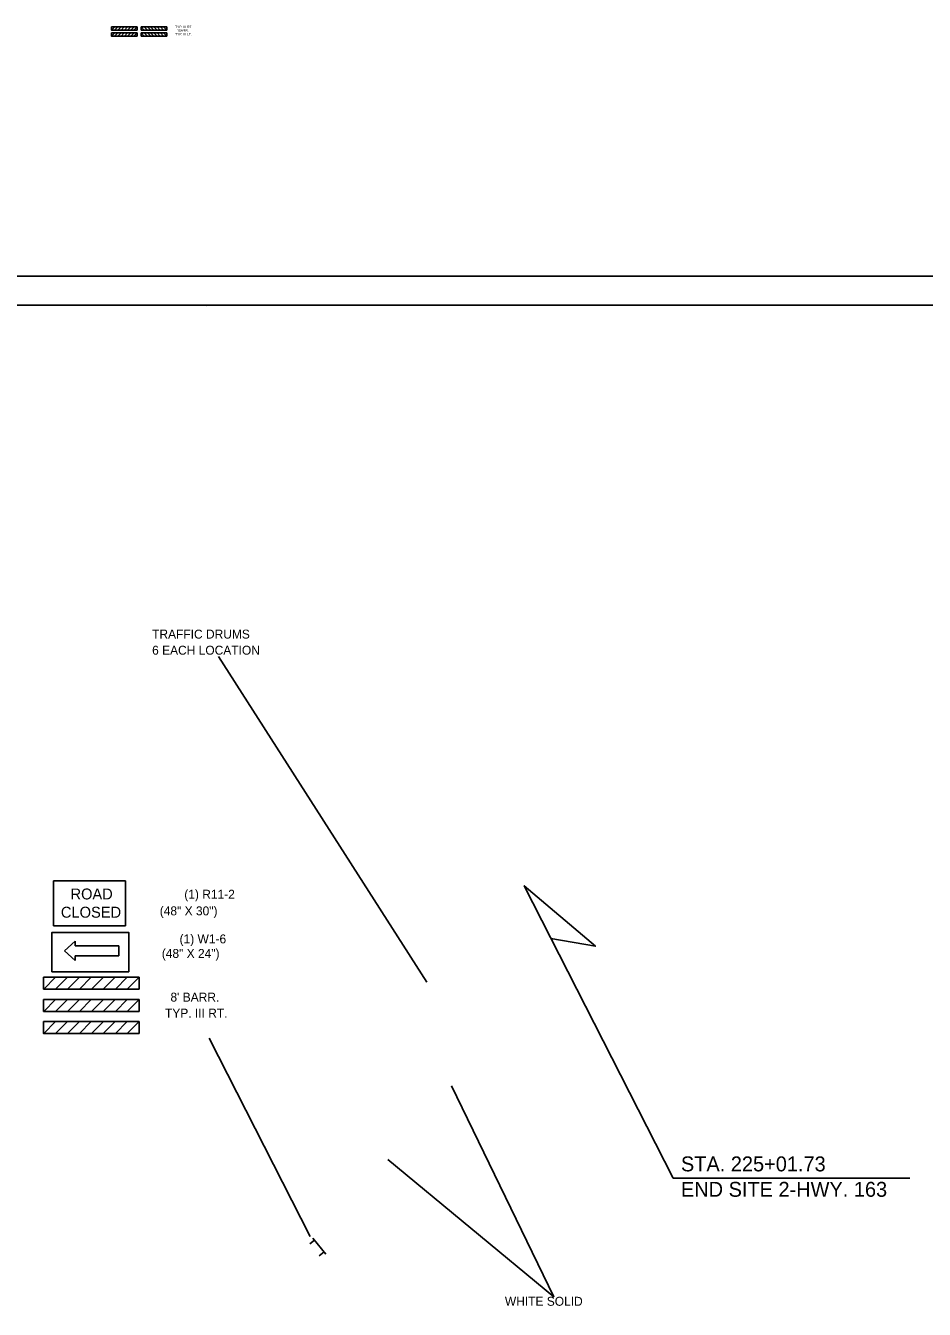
# Model space of a CAD drawing. Extents: x 1678017 to 1687792, y 404433 to 413488.
# Drawn here: x 1682454 to 1683056, y 409484 to 410344 of the extents above; entities that cross this region are included whole.
import ezdxf

# ---------------------------------------------------------------- set-up
doc = ezdxf.new("R2010")
doc.units = 0
for name, color, linetype in [('Default', 7, 'Continuous'), ('S_BUILDING', 7, 'Continuous'), ('S_GRAVEL_ROAD', 7, 'Continuous'), ('S_STREAM', 7, 'Continuous')]:
    doc.layers.add(name, color=color, linetype=linetype)

msp = doc.modelspace()

# ---------------------------------------------------------------- linework, layer by layer
at = {"layer": 'Default'}
for p, q in [((1682582.96, 409921.64), (1682722.71, 409703.28)), ((1682576.67, 409665.79), (1682644.35, 409532.72)), ((1682887.63, 409571.96), (1683046.44, 409571.96))]:
    msp.add_line(p, q, dxfattribs=at)
msp.add_lwpolyline([(1682887.63, 409571.96), (1682787.92, 409767.83), (1682835.6, 409727.36), (1682805.82, 409732.48)], dxfattribs=at)
at = {"layer": 'S_BUILDING'}
for p, q in [((1681812.23, 410157.15), (1683393.13, 410157.15)), ((1682574.83, 410155.85), (1682574.83, 410155.85)), ((1682574.83, 410155.85), (1682574.83, 410155.85))]:
    msp.add_line(p, q, dxfattribs=at)
at = {"layer": 'S_GRAVEL_ROAD'}
for p, q in [((1682511.17, 410343.63), (1682528.46, 410343.63)), ((1682511.17, 410341.46), (1682511.17, 410343.63)), ((1682511.17, 410341.46), (1682528.46, 410341.46)), ((1682528.46, 410341.46), (1682528.46, 410343.63)), ((1682528.46, 410341.46), (1682528.46, 410343.63)), ((1682548.31, 410343.63), (1682531.03, 410343.63)), ((1682531.03, 410341.46), (1682531.03, 410343.63)), ((1682531.03, 410341.46), (1682531.03, 410343.63)), ((1682548.31, 410341.46), (1682531.03, 410341.46)), ((1682548.31, 410341.46), (1682548.31, 410343.63)), ((1682511.17, 410339.62), (1682528.46, 410339.62)), ((1682511.17, 410337.45), (1682511.17, 410339.62)), ((1682511.17, 410337.45), (1682528.46, 410337.45)), ((1682528.46, 410337.45), (1682528.46, 410339.62)), ((1682548.31, 410339.62), (1682531.03, 410339.62)), ((1682531.03, 410337.45), (1682531.03, 410339.62)), ((1682548.31, 410337.45), (1682531.03, 410337.45)), ((1682548.31, 410337.45), (1682548.31, 410339.62)), ((1682472.43, 409741), (1682472.43, 409771.18)), ((1682472.43, 409771.18), (1682520.73, 409771.18)), ((1682520.73, 409741), (1682520.73, 409771.18)), ((1682472.43, 409741), (1682520.73, 409741)), ((1682479.67, 409724.27), (1682486.84, 409730.81)), ((1682486.84, 409727.54), (1682486.84, 409730.81)), ((1682486.84, 409717.72), (1682479.67, 409724.27)), ((1682516.23, 409727.54), (1682486.84, 409727.54)), ((1682516.23, 409720.99), (1682486.84, 409720.99)), ((1682486.84, 409720.99), (1682486.84, 409717.72)), ((1682516.23, 409720.99), (1682516.23, 409727.54)), ((1682465.65, 409706.59), (1682529.71, 409706.59)), ((1682465.65, 409698.54), (1682465.65, 409706.59)), ((1682529.71, 409698.54), (1682529.71, 409706.59)), ((1682465.65, 409698.54), (1682529.71, 409698.54)), ((1682529.66, 409698.57), (1682529.71, 409698.61)), ((1682465.65, 409691.67), (1682529.71, 409691.67)), ((1682465.65, 409683.65), (1682465.65, 409691.67)), ((1682529.71, 409683.65), (1682529.71, 409691.67)), ((1682529.71, 409683.65), (1682529.71, 409691.67)), ((1682465.65, 409683.65), (1682529.71, 409683.65)), ((1682465.65, 409676.81), (1682529.71, 409676.81)), ((1682465.65, 409668.79), (1682465.65, 409676.81)), ((1682529.71, 409668.79), (1682529.71, 409676.81)), ((1682465.65, 409668.79), (1682529.71, 409668.79)), ((1682646.27, 409531.71), (1682654.99, 409520.96)), ((1682647.37, 409530.36), (1682644.11, 409527.72)), ((1682653.8, 409522.42), (1682650.54, 409519.78))]:
    msp.add_line(p, q, dxfattribs=at)
for points in [[(1682515.5, 410343.63), (1682513.38, 410343.62), (1682511.22, 410341.46), (1682513.34, 410341.46)], [(1682519.82, 410343.63), (1682517.7, 410343.62), (1682515.54, 410341.46), (1682517.66, 410341.46)], [(1682524.14, 410343.63), (1682522.02, 410343.62), (1682519.86, 410341.46), (1682521.98, 410341.46)], [(1682528.46, 410343.63), (1682526.34, 410343.62), (1682524.18, 410341.46), (1682526.3, 410341.46)], [(1682531.03, 410343.63), (1682533.15, 410343.62), (1682535.31, 410341.46), (1682533.19, 410341.46)], [(1682535.35, 410343.63), (1682537.47, 410343.62), (1682539.63, 410341.46), (1682537.51, 410341.46)], [(1682539.67, 410343.63), (1682541.79, 410343.62), (1682543.95, 410341.46), (1682541.83, 410341.46)], [(1682543.99, 410343.63), (1682546.11, 410343.62), (1682548.27, 410341.46), (1682546.15, 410341.46)], [(1682515.5, 410339.62), (1682513.38, 410339.61), (1682511.22, 410337.45), (1682513.34, 410337.45)], [(1682519.82, 410339.62), (1682517.7, 410339.61), (1682515.54, 410337.45), (1682517.66, 410337.45)], [(1682524.14, 410339.62), (1682522.02, 410339.61), (1682519.86, 410337.45), (1682521.98, 410337.45)], [(1682528.46, 410339.62), (1682526.34, 410339.61), (1682524.18, 410337.45), (1682526.3, 410337.45)], [(1682531.03, 410339.62), (1682533.15, 410339.61), (1682535.31, 410337.45), (1682533.19, 410337.45)], [(1682535.35, 410339.62), (1682537.47, 410339.61), (1682539.63, 410337.45), (1682537.51, 410337.45)], [(1682539.67, 410339.62), (1682541.79, 410339.61), (1682543.95, 410337.45), (1682541.83, 410337.45)], [(1682543.99, 410339.62), (1682546.11, 410339.61), (1682548.27, 410337.45), (1682546.15, 410337.45)], [(1682471.27, 409710.23), (1682522.8, 409710.23), (1682522.8, 409736.58), (1682471.27, 409736.58)], [(1682481.69, 409706.59), (1682473.81, 409706.56), (1682465.82, 409698.57), (1682473.67, 409698.57)], [(1682497.7, 409706.59), (1682489.82, 409706.56), (1682481.82, 409698.57), (1682489.68, 409698.57)], [(1682513.7, 409706.59), (1682505.83, 409706.56), (1682497.83, 409698.57), (1682505.68, 409698.57)], [(1682529.71, 409706.59), (1682521.84, 409706.56), (1682513.84, 409698.57), (1682521.69, 409698.57)], [(1682481.69, 409691.67), (1682473.81, 409691.65), (1682465.82, 409683.65), (1682473.67, 409683.65)], [(1682497.7, 409691.67), (1682489.82, 409691.65), (1682481.82, 409683.65), (1682489.68, 409683.65)], [(1682513.7, 409691.67), (1682505.83, 409691.65), (1682497.83, 409683.65), (1682505.68, 409683.65)], [(1682529.71, 409691.67), (1682521.84, 409691.65), (1682513.84, 409683.65), (1682521.69, 409683.65)], [(1682481.69, 409676.81), (1682473.81, 409676.79), (1682465.82, 409668.79), (1682473.67, 409668.79)], [(1682497.7, 409676.81), (1682489.82, 409676.79), (1682481.82, 409668.79), (1682489.68, 409668.79)], [(1682513.7, 409676.81), (1682505.83, 409676.79), (1682497.83, 409668.79), (1682505.68, 409668.79)], [(1682529.71, 409676.81), (1682521.84, 409676.79), (1682513.84, 409668.79), (1682521.69, 409668.79)]]:
    msp.add_lwpolyline(points, close=True, dxfattribs=at)
at = {"layer": 'S_STREAM'}
msp.add_line((1681750.23, 410176.62), (1683416.9, 410176.62), dxfattribs=at)
for points in [[(1681750.2, 410176.62), (1683416.9, 410176.62), (1683416.9, 409109.93), (1681750.2, 409109.93)], [(1682981.83, 410157.15), (1683079.93, 410157.15), (1683079.93, 410107.75), (1683160.49, 410107.75), (1683276.49, 410107.75), (1683276.49, 409986.09), (1683393.13, 409986.09), (1683393.13, 409129.85), (1681812.23, 409129.85), (1681812.23, 410157.15)], [(1682981.83, 410157.15), (1683079.93, 410157.15), (1683079.93, 410107.75), (1683160.49, 410107.75), (1683276.49, 410107.75), (1683276.49, 409986.09), (1683393.13, 409986.09), (1683393.13, 409129.85), (1681812.23, 409129.85), (1681812.23, 410157.15)]]:
    msp.add_lwpolyline(points, close=True, dxfattribs=at)
msp.add_lwpolyline([(1682696.48, 409584.4), (1682807.66, 409492.32), (1682739.06, 409633.68)], dxfattribs=at)

# ---------------------------------------------------------------- texts
at = {"layer": 'Default'}
for s, height, p in [('TRAFFIC DRUMS', 6, (1682538.46, 409933.57)), ('6 EACH LOCATION', 6, (1682538.46, 409922.77)), ('STA. 225+01.73', 10, (1682892.93, 409576.41)), ('END SITE 2-HWY. 163', 10, (1682892.93, 409559.37))]:
    msp.add_text(s, height=height, dxfattribs=at).set_placement(p)
at = {"layer": 'S_GRAVEL_ROAD'}
for s, height, p in [('TYP. III RT.', 1.62, (1682553.82, 410342.81)), ("  ' BARR.", 1.62, (1682553.82, 410340.38)), ('TYP. III LT.', 1.62, (1682553.82, 410337.95)), ('ROAD', 7.312, (1682483.79, 409758.7)), ('(1) R11-2', 6, (1682560.02, 409759.18)), ('CLOSED', 7.348, (1682477.31, 409746.46)), ('(48" X 30")', 6, (1682543.58, 409748.03)), ('(1) W1-6', 6, (1682556.88, 409729.25)), ('(48" X 24")', 6, (1682544.95, 409719.5)), ("8' BARR.", 6, (1682550.76, 409690.21)), ('TYP. III RT.', 6, (1682547.1, 409679.49))]:
    msp.add_text(s, height=height, dxfattribs=at).set_placement(p)
at = {"layer": 'S_STREAM'}
msp.add_text('WHITE SOLID', height=6, dxfattribs=at).set_placement((1682774.93, 409486.32))

doc.saveas('drawing.dxf')
